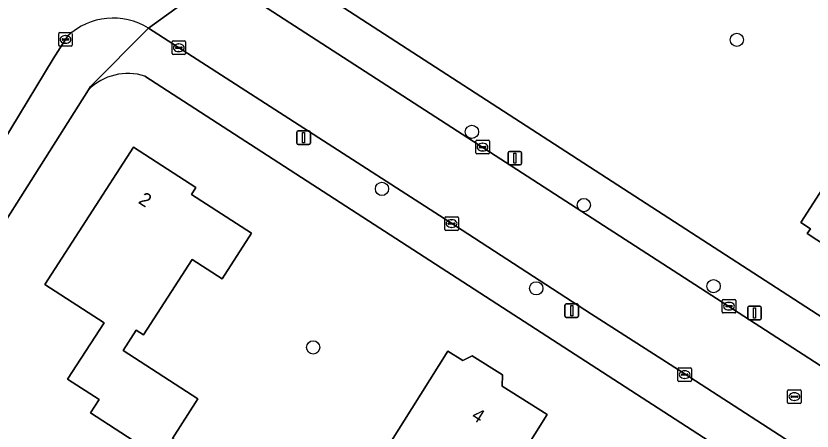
# Model space of a CAD drawing. Extents: x 161139 to 161601, y 381708 to 382245.
# Drawn here: x 161296.5 to 161355.3, y 382048.2 to 382078.8 of the extents above; entities that cross this region are included whole.
import ezdxf

# ---------------------------------------------------------------- set-up
doc = ezdxf.new("R2010")
doc.units = 0
for name, color, linetype in [('IMGEO_Boom', 7, 'Continuous'), ('IMGEO_Erf', 7, 'Continuous'), ('IMGEO_Kolk', 7, 'Continuous'), ('IMGEO_Lichtmast', 7, 'Continuous'), ('IMGEO_Pand', 7, 'Continuous'), ('IMGEO_Pand_nummerreeks', 7, 'Continuous'), ('IMGEO_Rijbaan_lokaal_open', 7, 'Continuous'), ('IMGEO_Rioolput', 7, 'Continuous'), ('IMGEO_Voetpad_open', 7, 'Continuous')]:
    doc.layers.add(name, color=color, linetype=linetype)

msp = doc.modelspace()

# ---------------------------------------------------------------- linework, layer by layer
at = {"layer": 'IMGEO_Boom'}
for centre in [(161349.751, 382077.022), (161330.202, 382070.239), (161323.56, 382066.027), (161338.459, 382064.833), (161334.95, 382058.691), (161348.037, 382058.854), (161318.485, 382054.336)]:
    msp.add_circle(centre, 0.489, dxfattribs=at)
at = {"layer": 'IMGEO_Erf'}
for points in [[(161320.525, 382089.631), (161313.623, 382083.997), (161443.483, 382000), (161462.38, 381987.777), (161470.3, 382000), (161498.24, 382043.117), (161359.011, 382133.266)], [(161421.048, 382000), (161306.066, 382074.349)], [(161301.893, 382073.339), (161290.838, 382055.877), (161287.538, 382048.363), (161285.187, 382041.077), (161283.628, 382034.817), (161278.294, 382002.287), (161281.877, 382000), (161299.823, 381988.353), (161310.674, 381981.109), (161322.611, 381973.432), (161322.712, 381973.551), (161378.924, 381936.994), (161385.641, 381932.206), (161392.817, 381926.552), (161429.313, 381896.994)], [(161302.036, 382049.498), (161302.677, 382050.489), (161300.358, 382051.989), (161303.045, 382056.146), (161298.669, 382058.976), (161305.221, 382069.111), (161309.823, 382066.136), (161309.493, 382065.626), (161313.942, 382062.75), (161311.764, 382059.381), (161309.556, 382060.808), (161305.969, 382055.257), (161305.428, 382055.607), (161304.454, 382054.101), (161309.98, 382050.528), (161308.099, 382047.617), (161311.312, 382045.54), (161312.444, 382047.29), (161313.843, 382046.386)], [(161357.171, 382061.289), (161354.949, 382062.728), (161355.18, 382063.085), (161354.467, 382063.546), (161357.185, 382067.744)], [(161315.233, 382046.758), (161317.706, 382045.158), (161314.844, 382040.73), (161309.038, 382044.479), (161309.262, 382044.827), (161302.036, 382049.498)]]:
    msp.add_lwpolyline(points, dxfattribs=at)
msp.add_lwpolyline([(161330.891, 382030.671), (161328.144, 382032.397), (161327.326, 382031.094), (161327.227, 382031.156), (161324.172, 382033.077), (161327.053, 382037.661), (161320.18, 382041.981), (161322.293, 382045.342), (161322.758, 382045.049), (161325.756, 382049.819), (161328.417, 382054.052), (161329.525, 382053.356), (161330.221, 382053.724), (161332.458, 382052.318), (161332.427, 382051.481), (161335.761, 382049.386), (161329.259, 382039.042), (161331.435, 382037.66), (161334.21, 382035.898)], close=True, dxfattribs=at)
msp.add_arc((161304.814, 382070.394), 4.148, 72.4386, 134.77295, dxfattribs=at)
at = {"layer": 'IMGEO_Kolk'}
for p, q in [((161299.698, 382076.627), (161299.698, 382077.479)), ((161299.773, 382077.553), (161300.625, 382077.553)), ((161300.186, 382077.333), (161300.211, 382077.333)), ((161300.699, 382077.479), (161300.699, 382076.627)), ((161300.625, 382076.553), (161299.773, 382076.553)), ((161299.957, 382077.047), (161299.957, 382077.059)), ((161300.395, 382077.01), (161299.997, 382077.01)), ((161300, 382077.096), (161300.398, 382077.096)), ((161300.209, 382076.773), (161300.184, 382076.773)), ((161300.441, 382077.059), (161300.441, 382077.047)), ((161308.065, 382076.013), (161308.065, 382076.865)), ((161308.14, 382076.939), (161308.992, 382076.939)), ((161308.553, 382076.719), (161308.578, 382076.719)), ((161309.066, 382076.865), (161309.066, 382076.013)), ((161308.324, 382076.433), (161308.324, 382076.445)), ((161308.762, 382076.396), (161308.364, 382076.396)), ((161308.367, 382076.482), (161308.765, 382076.482)), ((161308.576, 382076.159), (161308.551, 382076.159)), ((161308.808, 382076.445), (161308.808, 382076.433)), ((161308.992, 382075.939), (161308.14, 382075.939)), ((161330.485, 382068.685), (161330.485, 382069.537)), ((161330.56, 382069.611), (161331.412, 382069.611)), ((161331.486, 382069.537), (161331.486, 382068.685)), ((161330.744, 382069.105), (161330.744, 382069.117)), ((161331.182, 382069.068), (161330.784, 382069.068)), ((161330.787, 382069.154), (161331.185, 382069.154)), ((161330.973, 382069.391), (161330.998, 382069.391)), ((161331.228, 382069.117), (161331.228, 382069.105)), ((161331.412, 382068.611), (161330.56, 382068.611)), ((161330.996, 382068.831), (161330.971, 382068.831)), ((161328.198, 382063.042), (161328.198, 382063.894)), ((161328.273, 382063.968), (161329.125, 382063.968)), ((161328.686, 382063.748), (161328.711, 382063.748)), ((161329.199, 382063.894), (161329.199, 382063.042)), ((161328.457, 382063.462), (161328.457, 382063.474)), ((161328.895, 382063.425), (161328.497, 382063.425)), ((161328.5, 382063.511), (161328.898, 382063.511)), ((161328.709, 382063.188), (161328.684, 382063.188)), ((161328.941, 382063.474), (161328.941, 382063.462)), ((161329.125, 382062.968), (161328.273, 382062.968)), ((161348.679, 382056.948), (161348.679, 382057.8)), ((161348.754, 382057.874), (161349.606, 382057.874)), ((161349.68, 382057.8), (161349.68, 382056.948)), ((161348.938, 382057.368), (161348.938, 382057.38)), ((161349.376, 382057.331), (161348.978, 382057.331)), ((161348.981, 382057.417), (161349.379, 382057.417)), ((161349.167, 382057.654), (161349.192, 382057.654)), ((161349.422, 382057.38), (161349.422, 382057.368)), ((161349.606, 382056.874), (161348.754, 382056.874)), ((161349.19, 382057.094), (161349.165, 382057.094)), ((161345.399, 382051.898), (161345.399, 382052.75)), ((161345.474, 382052.824), (161346.326, 382052.824)), ((161345.887, 382052.604), (161345.912, 382052.604)), ((161346.4, 382052.75), (161346.4, 382051.898)), ((161345.658, 382052.318), (161345.658, 382052.33)), ((161346.096, 382052.281), (161345.698, 382052.281)), ((161345.701, 382052.367), (161346.099, 382052.367)), ((161345.91, 382052.044), (161345.885, 382052.044)), ((161346.142, 382052.33), (161346.142, 382052.318)), ((161346.326, 382051.824), (161345.474, 382051.824))]:
    msp.add_line(p, q, dxfattribs=at)
for points in [[(161299.698, 382076.627), (161299.698, 382077.479)], [(161299.773, 382077.553), (161300.625, 382077.553)], [(161300.699, 382077.479), (161300.699, 382076.627)], [(161300.625, 382076.553), (161299.773, 382076.553)], [(161308.065, 382076.013), (161308.065, 382076.865)], [(161308.14, 382076.939), (161308.992, 382076.939)], [(161309.066, 382076.865), (161309.066, 382076.013)], [(161308.992, 382075.939), (161308.14, 382075.939)], [(161330.485, 382068.685), (161330.485, 382069.537)], [(161330.56, 382069.611), (161331.412, 382069.611)], [(161331.486, 382069.537), (161331.486, 382068.685)], [(161331.412, 382068.611), (161330.56, 382068.611)], [(161328.198, 382063.042), (161328.198, 382063.894)], [(161328.273, 382063.968), (161329.125, 382063.968)], [(161329.199, 382063.894), (161329.199, 382063.042)], [(161329.125, 382062.968), (161328.273, 382062.968)], [(161348.679, 382056.948), (161348.679, 382057.8)], [(161348.754, 382057.874), (161349.606, 382057.874)], [(161349.68, 382057.8), (161349.68, 382056.948)], [(161349.606, 382056.874), (161348.754, 382056.874)], [(161345.399, 382051.898), (161345.399, 382052.75)], [(161345.474, 382052.824), (161346.326, 382052.824)], [(161346.4, 382052.75), (161346.4, 382051.898)], [(161346.326, 382051.824), (161345.474, 382051.824)]]:
    msp.add_lwpolyline(points, dxfattribs=at)
for centre, radius, start, end in [((161299.775, 382077.477), 0.0765, 91.55205, 178.44795), ((161299.775, 382077.477), 0.0765, 91.55205, 178.44795), ((161300.623, 382077.477), 0.0765, 1.55205, 88.44795), ((161300.623, 382077.477), 0.0765, 1.55205, 88.44795), ((161299.775, 382076.629), 0.0765, 181.55205, 268.44795), ((161299.775, 382076.629), 0.0765, 181.55205, 268.44795), ((161299.997, 382077.056), 0.0403, 85.87752, 175.75265), ((161299.994, 382077.046), 0.0366, 178.93798, 274.71019), ((161300.398, 382077.053), 0.043, 264.86636, 352.45326), ((161300.402, 382077.058), 0.0386, 1.73085, 96.63898), ((161300.623, 382076.629), 0.0765, 271.55205, 358.44795), ((161300.623, 382076.629), 0.0765, 271.55205, 358.44795), ((161308.142, 382076.863), 0.0765, 91.55205, 178.44795), ((161308.142, 382076.863), 0.0765, 91.55205, 178.44795), ((161308.99, 382076.863), 0.0765, 1.55205, 88.44795), ((161308.99, 382076.863), 0.0765, 1.55205, 88.44795), ((161308.142, 382076.015), 0.0765, 181.55205, 268.44795), ((161308.142, 382076.015), 0.0765, 181.55205, 268.44795), ((161308.364, 382076.442), 0.0403, 85.87752, 175.75265), ((161308.361, 382076.432), 0.0366, 178.93798, 274.71019), ((161308.765, 382076.439), 0.043, 264.86636, 352.45326), ((161308.769, 382076.444), 0.0386, 1.73085, 96.63898), ((161308.99, 382076.015), 0.0765, 271.55205, 358.44795), ((161308.99, 382076.015), 0.0765, 271.55205, 358.44795), ((161330.562, 382069.535), 0.0765, 91.55205, 178.44795), ((161330.562, 382069.535), 0.0765, 91.55205, 178.44795), ((161331.41, 382069.535), 0.0765, 1.55205, 88.44795), ((161331.41, 382069.535), 0.0765, 1.55205, 88.44795), ((161330.784, 382069.114), 0.0403, 85.87752, 175.75265), ((161330.781, 382069.104), 0.0366, 178.93798, 274.71019), ((161331.185, 382069.111), 0.043, 264.86636, 352.45326), ((161331.189, 382069.116), 0.0386, 1.73085, 96.63898), ((161330.562, 382068.687), 0.0765, 181.55205, 268.44795), ((161330.562, 382068.687), 0.0765, 181.55205, 268.44795), ((161331.41, 382068.687), 0.0765, 271.55205, 358.44795), ((161331.41, 382068.687), 0.0765, 271.55205, 358.44795), ((161328.275, 382063.892), 0.0765, 91.55205, 178.44795), ((161328.275, 382063.892), 0.0765, 91.55205, 178.44795), ((161329.123, 382063.892), 0.0765, 1.55205, 88.44795), ((161329.123, 382063.892), 0.0765, 1.55205, 88.44795), ((161328.275, 382063.044), 0.0765, 181.55205, 268.44795), ((161328.275, 382063.044), 0.0765, 181.55205, 268.44795), ((161328.497, 382063.471), 0.0403, 85.87752, 175.75265), ((161328.494, 382063.461), 0.0366, 178.93798, 274.71019), ((161328.898, 382063.468), 0.043, 264.86636, 352.45326), ((161328.902, 382063.473), 0.0386, 1.73085, 96.63898), ((161329.123, 382063.044), 0.0765, 271.55205, 358.44795), ((161329.123, 382063.044), 0.0765, 271.55205, 358.44795), ((161348.756, 382057.798), 0.0765, 91.55205, 178.44795), ((161348.756, 382057.798), 0.0765, 91.55205, 178.44795), ((161349.604, 382057.798), 0.0765, 1.55205, 88.44795), ((161349.604, 382057.798), 0.0765, 1.55205, 88.44795), ((161348.978, 382057.377), 0.0403, 85.87752, 175.75265), ((161348.975, 382057.367), 0.0366, 178.93798, 274.71019), ((161349.379, 382057.374), 0.043, 264.86636, 352.45326), ((161349.383, 382057.379), 0.0386, 1.73085, 96.63898), ((161348.756, 382056.95), 0.0765, 181.55205, 268.44795), ((161348.756, 382056.95), 0.0765, 181.55205, 268.44795), ((161349.604, 382056.95), 0.0765, 271.55205, 358.44795), ((161349.604, 382056.95), 0.0765, 271.55205, 358.44795), ((161345.476, 382052.748), 0.0765, 91.55205, 178.44795), ((161345.476, 382052.748), 0.0765, 91.55205, 178.44795), ((161346.324, 382052.748), 0.0765, 1.55205, 88.44795), ((161346.324, 382052.748), 0.0765, 1.55205, 88.44795), ((161345.476, 382051.9), 0.0765, 181.55205, 268.44795), ((161345.476, 382051.9), 0.0765, 181.55205, 268.44795), ((161345.698, 382052.327), 0.0403, 85.87752, 175.75265), ((161345.695, 382052.317), 0.0366, 178.93798, 274.71019), ((161346.099, 382052.324), 0.043, 264.86636, 352.45326), ((161346.103, 382052.329), 0.0386, 1.73085, 96.63898), ((161346.324, 382051.9), 0.0765, 271.55205, 358.44795), ((161346.324, 382051.9), 0.0765, 271.55205, 358.44795)]:
    msp.add_arc(centre, radius, start, end, dxfattribs=at)
for centre, major_axis, ratio, start_param, end_param in [((161300.185, 382077.053), (-0.387, 0.002), 0.722429, 4.712389, 7.853982), ((161300.21, 382077.053), (-0.39, 0.002), 0.717154, 1.570796, 4.712389), ((161308.552, 382076.439), (-0.387, 0.002), 0.722429, 4.712389, 7.853982), ((161308.577, 382076.439), (-0.39, 0.002), 0.717154, 1.570796, 4.712389), ((161330.972, 382069.111), (-0.387, 0.002), 0.722429, 4.712389, 7.853982), ((161330.997, 382069.111), (-0.39, 0.002), 0.717154, 1.570796, 4.712389), ((161328.685, 382063.468), (-0.387, 0.002), 0.722429, 4.712389, 7.853982), ((161328.71, 382063.468), (-0.39, 0.002), 0.717154, 1.570796, 4.712389), ((161349.166, 382057.374), (-0.387, 0.002), 0.722429, 4.712389, 7.853982), ((161349.191, 382057.374), (-0.39, 0.002), 0.717154, 1.570796, 4.712389), ((161345.886, 382052.324), (-0.387, 0.002), 0.722429, 4.712389, 7.853982), ((161345.911, 382052.324), (-0.39, 0.002), 0.717154, 1.570796, 4.712389)]:
    msp.add_ellipse(centre, major_axis=major_axis, ratio=ratio, start_param=start_param, end_param=end_param, dxfattribs=at)
at = {"layer": 'IMGEO_Lichtmast'}
for p, q in [((161317.284, 382069.41), (161317.284, 382070.21)), ((161317.284, 382070.21), (161317.284, 382069.41)), ((161317.384, 382070.31), (161318.174, 382070.31)), ((161318.174, 382070.31), (161317.384, 382070.31)), ((161318.274, 382070.21), (161318.274, 382069.41)), ((161318.274, 382069.41), (161318.274, 382070.21)), ((161318.174, 382069.31), (161317.384, 382069.31)), ((161317.384, 382069.31), (161318.174, 382069.31)), ((161332.881, 382067.893), (161332.881, 382068.693)), ((161332.881, 382068.693), (161332.881, 382067.893)), ((161332.981, 382068.793), (161333.771, 382068.793)), ((161333.771, 382068.793), (161332.981, 382068.793)), ((161333.871, 382068.693), (161333.871, 382067.893)), ((161333.871, 382067.893), (161333.871, 382068.693)), ((161333.771, 382067.793), (161332.981, 382067.793)), ((161332.981, 382067.793), (161333.771, 382067.793)), ((161337.069, 382056.647), (161337.069, 382057.447)), ((161337.069, 382057.447), (161337.069, 382056.647)), ((161337.169, 382057.547), (161337.959, 382057.547)), ((161337.959, 382057.547), (161337.169, 382057.547)), ((161338.059, 382057.447), (161338.059, 382056.647)), ((161338.059, 382056.647), (161338.059, 382057.447)), ((161350.572, 382056.473), (161350.572, 382057.273)), ((161350.572, 382057.273), (161350.572, 382056.473)), ((161350.672, 382057.373), (161351.462, 382057.373)), ((161351.462, 382057.373), (161350.672, 382057.373)), ((161351.562, 382057.273), (161351.562, 382056.473)), ((161351.562, 382056.473), (161351.562, 382057.273)), ((161337.959, 382056.547), (161337.169, 382056.547)), ((161337.169, 382056.547), (161337.959, 382056.547)), ((161351.462, 382056.373), (161350.672, 382056.373)), ((161350.672, 382056.373), (161351.462, 382056.373))]:
    msp.add_line(p, q, dxfattribs=at)
for points in [[(161317.704, 382070.185), (161317.854, 382070.185), (161317.854, 382069.435), (161317.704, 382069.435), (161317.704, 382070.185)], [(161333.301, 382068.668), (161333.451, 382068.668), (161333.451, 382067.918), (161333.301, 382067.918), (161333.301, 382068.668)], [(161337.489, 382057.422), (161337.639, 382057.422), (161337.639, 382056.672), (161337.489, 382056.672), (161337.489, 382057.422)], [(161350.992, 382057.248), (161351.142, 382057.248), (161351.142, 382056.498), (161350.992, 382056.498), (161350.992, 382057.248)]]:
    msp.add_lwpolyline(points, dxfattribs=at)
for centre, start, end in [((161317.384, 382070.21), 90, 180), ((161317.384, 382070.21), 90, 180), ((161318.174, 382070.21), 0, 90), ((161318.174, 382070.21), 360, 90), ((161317.384, 382069.41), 180, 270), ((161317.384, 382069.41), 180, 270), ((161318.174, 382069.41), 270, 0), ((161318.174, 382069.41), 270, 0), ((161332.981, 382068.693), 90, 180), ((161332.981, 382068.693), 90, 180), ((161333.771, 382068.693), 0, 90), ((161333.771, 382068.693), 360, 90), ((161332.981, 382067.893), 180, 270), ((161332.981, 382067.893), 180, 270), ((161333.771, 382067.893), 270, 0), ((161333.771, 382067.893), 270, 0), ((161337.169, 382057.447), 90, 180), ((161337.169, 382057.447), 90, 180), ((161337.959, 382057.447), 0, 90), ((161337.959, 382057.447), 360, 90), ((161350.672, 382057.273), 90, 180), ((161350.672, 382057.273), 90, 180), ((161351.462, 382057.273), 0, 90), ((161351.462, 382057.273), 360, 90), ((161337.169, 382056.647), 180, 270), ((161337.169, 382056.647), 180, 270), ((161337.959, 382056.647), 270, 0), ((161337.959, 382056.647), 270, 0), ((161350.672, 382056.473), 180, 270), ((161350.672, 382056.473), 180, 270), ((161351.462, 382056.473), 270, 0), ((161351.462, 382056.473), 270, 0)]:
    msp.add_arc(centre, 0.1, start, end, dxfattribs=at)
at = {"layer": 'IMGEO_Pand'}
for points in [[(161373.678, 382073.088), (161373.506, 382073.199), (161373.234, 382072.779), (161367.586, 382076.436), (161363.625, 382070.32), (161360.263, 382072.498), (161357.185, 382067.744), (161354.467, 382063.546), (161355.18, 382063.085), (161354.949, 382062.728), (161357.171, 382061.289), (161357.399, 382061.642), (161361.193, 382059.186), (161367.026, 382068.194), (161367.614, 382067.814), (161368.301, 382068.878), (161370.156, 382067.673)], [(161327.227, 382031.156), (161331.435, 382037.66), (161329.259, 382039.042), (161335.761, 382049.386), (161332.427, 382051.481), (161332.458, 382052.318), (161330.221, 382053.724), (161329.525, 382053.356), (161328.417, 382054.052), (161325.756, 382049.819), (161322.758, 382045.049), (161322.293, 382045.342), (161320.18, 382041.981), (161327.053, 382037.661), (161324.172, 382033.077)]]:
    msp.add_lwpolyline(points, close=True, dxfattribs=at)
for points in [[(161313.942, 382062.75), (161309.493, 382065.626), (161309.823, 382066.136), (161305.221, 382069.111), (161298.669, 382058.976), (161303.045, 382056.146), (161300.358, 382051.989), (161302.677, 382050.489), (161302.036, 382049.498), (161309.262, 382044.827), (161309.038, 382044.479), (161314.844, 382040.73), (161317.706, 382045.158), (161315.233, 382046.758)], [(161313.843, 382046.386), (161312.444, 382047.29), (161311.312, 382045.54), (161308.099, 382047.617), (161309.98, 382050.528), (161304.454, 382054.101), (161305.428, 382055.607), (161305.969, 382055.257), (161309.556, 382060.808), (161311.764, 382059.381), (161313.942, 382062.75)]]:
    msp.add_lwpolyline(points, dxfattribs=at)
at = {"layer": 'IMGEO_Rijbaan_lokaal_open'}
for points in [[(161375.585, 382040.285), (161362.411, 382048.813), (161356.674, 382052.498), (161311.536, 382081.664), (161306.338, 382077.878), (161325.321, 382065.668), (161328.504, 382063.628), (161339.032, 382056.795), (161345.442, 382052.667), (161359.944, 382043.32), (161366.307, 382039.161), (161381.679, 382029.228), (161388.068, 382025.069), (161398.439, 382018.395)], [(161306.338, 382077.878), (161311.536, 382081.664)], [(161286.714, 382054.067), (161288.423, 382057.491), (161289.88, 382060.122), (161299.28, 382075.613), (161300.362, 382077.308)]]:
    msp.add_lwpolyline(points, dxfattribs=at)
msp.add_arc((161303.722, 382073.688), 4.939, 58.02568, 132.87127, dxfattribs=at)
at = {"layer": 'IMGEO_Rioolput'}
for p, q in [((161353.504, 382050.276), (161353.504, 382051.128)), ((161353.579, 382051.202), (161354.431, 382051.202)), ((161353.763, 382050.696), (161353.763, 382050.708)), ((161353.806, 382050.745), (161354.204, 382050.745)), ((161353.992, 382050.982), (161354.017, 382050.982)), ((161354.247, 382050.708), (161354.247, 382050.696)), ((161354.505, 382051.128), (161354.505, 382050.276)), ((161354.431, 382050.202), (161353.579, 382050.202)), ((161354.201, 382050.659), (161353.803, 382050.659)), ((161354.015, 382050.422), (161353.99, 382050.422))]:
    msp.add_line(p, q, dxfattribs=at)
for points in [[(161353.504, 382050.276), (161353.504, 382051.128)], [(161353.579, 382051.202), (161354.431, 382051.202)], [(161354.505, 382051.128), (161354.505, 382050.276)], [(161354.431, 382050.202), (161353.579, 382050.202)]]:
    msp.add_lwpolyline(points, dxfattribs=at)
for centre, radius, start, end in [((161353.581, 382051.126), 0.0765, 91.55205, 178.44795), ((161353.581, 382051.126), 0.0765, 91.55205, 178.44795), ((161353.803, 382050.705), 0.0403, 85.87752, 175.75265), ((161353.8, 382050.695), 0.0366, 178.93798, 274.71019), ((161354.204, 382050.702), 0.043, 264.86636, 352.45326), ((161354.208, 382050.707), 0.0386, 1.73085, 96.63898), ((161354.429, 382051.126), 0.0765, 1.55205, 88.44795), ((161354.429, 382051.126), 0.0765, 1.55205, 88.44795), ((161353.581, 382050.278), 0.0765, 181.55205, 268.44795), ((161353.581, 382050.278), 0.0765, 181.55205, 268.44795), ((161354.429, 382050.278), 0.0765, 271.55205, 358.44795), ((161354.429, 382050.278), 0.0765, 271.55205, 358.44795)]:
    msp.add_arc(centre, radius, start, end, dxfattribs=at)
for centre, major_axis, ratio, start_param, end_param in [((161353.991, 382050.702), (-0.387, 0.002), 0.722429, 4.712389, 7.853982), ((161354.016, 382050.702), (-0.39, 0.002), 0.717154, 1.570796, 4.712389)]:
    msp.add_ellipse(centre, major_axis=major_axis, ratio=ratio, start_param=start_param, end_param=end_param, dxfattribs=at)
at = {"layer": 'IMGEO_Voetpad_open'}
for points in [[(161313.623, 382083.997), (161311.536, 382081.664), (161356.674, 382052.498), (161362.411, 382048.813), (161375.585, 382040.285), (161382.572, 382035.748), (161395.928, 382027.083), (161402.927, 382022.535), (161416.852, 382013.552), (161420.042, 382011.494), (161421.741, 382010.379), (161425.551, 382007.922), (161458.647, 381986.439), (161460.91, 381984.988)], [(161464.955, 381985.959), (161462.38, 381987.777), (161443.483, 382000), (161313.623, 382083.997)], [(161287.538, 382048.363), (161290.838, 382055.877), (161301.893, 382073.339), (161302.036, 382073.583), (161306.338, 382077.878)], [(161398.439, 382018.395), (161388.068, 382025.069), (161381.679, 382029.228), (161366.307, 382039.161), (161359.944, 382043.32), (161345.442, 382052.667), (161339.032, 382056.795), (161328.504, 382063.628), (161325.321, 382065.668), (161306.338, 382077.878), (161302.036, 382073.583), (161301.893, 382073.339)], [(161300.362, 382077.308), (161299.28, 382075.613), (161289.88, 382060.122), (161288.423, 382057.491), (161288.868, 382057.264), (161287.159, 382053.84), (161286.714, 382054.067)], [(161306.066, 382074.349), (161421.048, 382000), (161474.804, 381965.241), (161478.068, 381963.057), (161478.909, 381962.515)]]:
    msp.add_lwpolyline(points, dxfattribs=at)
for centre, radius, start, end in [((161303.722, 382073.688), 4.939, 58.02568, 132.87127), ((161304.814, 382070.394), 4.148, 72.4386, 134.77295)]:
    msp.add_arc(centre, radius, start, end, dxfattribs=at)

# ---------------------------------------------------------------- texts
at = {"layer": 'IMGEO_Pand_nummerreeks'}
for s, rotation, p in [('2', 327.11795, (161305.51, 382065.02)), ('4', 327.57022, (161330.098, 382049.098))]:
    msp.add_text(s, height=1, rotation=rotation, dxfattribs=at).set_placement(p)

doc.saveas('drawing.dxf')
